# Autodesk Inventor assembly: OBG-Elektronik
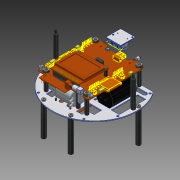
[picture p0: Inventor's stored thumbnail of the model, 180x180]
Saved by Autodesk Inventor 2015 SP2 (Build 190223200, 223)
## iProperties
Created: 2012-08
Part Number: OBG-Elektronik
Document SubType Name: Assembly
Designer: rYan
Mass: 772.839 g
Surface Area: 1589.28 cm^2
Volume: 316.547 cm^3
Density: 2.44147 g/cm^3
Author: rYan
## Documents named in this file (14)
- D:\TIGERs GIT\Hardware\mechanik\2016\Inventor\Elektronik\OBG-Elektronik.iam
- D:\TIGERs GIT\Hardware\mechanik\2016\Inventor\Elektronik\Elektronikhalter.ipt
- E:\Tigers SVN\mechanik\2013\Inventor\Kaufteile\Abstandsbolzen Typ A.ipt
- D:\TIGERs GIT\Hardware\mechanik\2016\Inventor\Elektronik\UBG-Mainboard.iam
- E:\Tigers SVN\mechanik\2013\Inventor\Kaufteile\Abstandsbolzen Typ B.ipt
- D:\TIGERs GIT\Hardware\mechanik\2016\Inventor\Inhaltscenter\en-US\DIN 7984\DIN 7984 - M4 x 6.ipt
- D:\TIGERs GIT\Hardware\mechanik\2016\Inventor\Inhaltscenter\en-US\DIN 7984\DIN 7984 - M3 x 6.ipt
- D:\TIGERs GIT\Hardware\mechanik\2016\Inventor\Kaufteile\Kondensator 30x50.ipt
- D:\TIGERs GIT\Hardware\mechanik\2016\Inventor\Kaufteile\Abstandsbolzen Typ B M3-8mm.ipt
- D:\TIGERs GIT\Hardware\mechanik\2016\Inventor\Elektronik\MG-Kickerboard.iam
- D:\TIGERs GIT\Hardware\mechanik\2016\Inventor\Kaufteile\Abstandsbolzen Typ A M4-65mm-SW8.ipt
- D:\TIGERs GIT\Hardware\mechanik\2016\Inventor\Kaufteile\Akku 4S1P 1800.ipt
- D:\TIGERs GIT\Hardware\mechanik\2016\Inventor\Kaufteile\Abstandsbolzen Typ B M3-30mm-SW6.ipt
- D:\TIGERs GIT\Hardware\mechanik\2016\Inventor\Kaufteile\Abstandsbolzen Typ B M4-55mm.ipt
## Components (31 placed, 11 different names)
1. Elektronikhalter:1 — Passend:152, Passend:288, Passend:289, Passend:290, Passend:291, Passend:292, Passend:293, Passend:294, Passend:295, Passend:296, Einfügen:7, Einfügen:8, Passend:356, Passend:357, Einfügen:9, Einfügen:10, Einfügen:11, Einfügen:12, Einfügen:15, Einfügen:16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
2. Akku 4S1P 1800:1 — Passend:359, Passend:360
3. UBG-Mainboard:1 [sub-assembly] — Einfügen:9, Einfügen:10
4. Abstandsbolzen Typ A M4-65mm-SW8:17 — Einfügen:8
5. Abstandsbolzen Typ A M4-65mm-SW8:18 — Einfügen:7
6. Abstandsbolzen Typ A M4-65mm-SW8:19 — Einfügen:12
7. Abstandsbolzen Typ A M4-65mm-SW8:20 — Einfügen:11
8. DIN 7984 M4 x 6:7 — Einfügen:15
9. DIN 7984 M4 x 6:8 — Einfügen:16
10. DIN 7984 M4 x 6:9 — Einfügen:18
11. DIN 7984 M4 x 6:10 — Einfügen:17
12. Abstandsbolzen Typ B M3-30mm-SW6:33 — Einfügen:22
13. Abstandsbolzen Typ B M3-30mm-SW6:34 — Einfügen:21
14. Abstandsbolzen Typ B M3-30mm-SW6:35 — Einfügen:23
15. Abstandsbolzen Typ B M3-30mm-SW6:36 — Einfügen:24
16. Abstandsbolzen Typ B M3-30mm-SW6:37 — Einfügen:25
17. Abstandsbolzen Typ B M4-55mm:38 — Einfügen:27
18. Abstandsbolzen Typ B M4-55mm:39 — Einfügen:26
19. DIN 7984 M4 x 6:5
20. DIN 7984 M4 x 6:6 — Passend:152
21. Kondensator 30x50:2 — Fluchtend:1, Fluchtend:3, Passend:357, Tangential:1, Passend:358
22. Kondensator 30x50:1 — Fluchtend:1, Fluchtend:3, Passend:356
23. Abstandsbolzen Typ B M3-8mm:29 — Passend:288, Passend:295
24. Abstandsbolzen Typ B M3-8mm:30 — Passend:290, Passend:292, Passend:298
25. Abstandsbolzen Typ B M3-8mm:31 — Passend:289, Passend:293, Passend:297, Passend:300
26. Abstandsbolzen Typ B M3-8mm:32 — Passend:291, Passend:294
27. MG-Kickerboard:1 [sub-assembly] — Passend:296, Passend:297, Passend:298, Passend:299
28. DIN 7984 M3 x 6:9 — Passend:299, Passend:300
29. DIN 7984 M3 x 6:10
30. DIN 7984 M3 x 6:11
31. DIN 7984 M3 x 6:12
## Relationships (39: Mate 19, Insert 17, Flush 2, Tangent 1)
- Fluchtend:1 [Flush]: Kondensator 30x50:2 ↔ Kondensator 30x50:1
- Fluchtend:3 [Flush]: Kondensator 30x50:2 ↔ Kondensator 30x50:1
- Passend:152 [Mate]: Elektronikhalter:1 ↔ DIN 7984 M4 x 6:6
- Passend:288 [Mate]: Elektronikhalter:1 ↔ Abstandsbolzen Typ B M3-8mm:29
- Passend:289 [Mate]: Elektronikhalter:1 ↔ Abstandsbolzen Typ B M3-8mm:31
- Passend:290 [Mate]: Elektronikhalter:1 ↔ Abstandsbolzen Typ B M3-8mm:30
- Passend:291 [Mate]: Elektronikhalter:1 ↔ Abstandsbolzen Typ B M3-8mm:32
- Passend:292 [Mate]: Elektronikhalter:1 ↔ Abstandsbolzen Typ B M3-8mm:30
- Passend:293 [Mate]: Elektronikhalter:1 ↔ Abstandsbolzen Typ B M3-8mm:31
- Passend:294 [Mate]: Elektronikhalter:1 ↔ Abstandsbolzen Typ B M3-8mm:32
- Passend:295 [Mate]: Elektronikhalter:1 ↔ Abstandsbolzen Typ B M3-8mm:29
- Passend:296 [Mate]: Elektronikhalter:1 ↔ MG-Kickerboard:1
- Passend:297 [Mate]: Abstandsbolzen Typ B M3-8mm:31 ↔ MG-Kickerboard:1
- Passend:298 [Mate]: Abstandsbolzen Typ B M3-8mm:30 ↔ MG-Kickerboard:1
- Passend:299 [Mate]: MG-Kickerboard:1 ↔ DIN 7984 M3 x 6:9
- Passend:300 [Mate]: Abstandsbolzen Typ B M3-8mm:31 ↔ DIN 7984 M3 x 6:9
- Einfügen:7 [Insert]: Elektronikhalter:1 ↔ Abstandsbolzen Typ A M4-65mm-SW8:18
- Einfügen:8 [Insert]: Elektronikhalter:1 ↔ Abstandsbolzen Typ A M4-65mm-SW8:17
- Passend:356 [Mate]: Elektronikhalter:1 ↔ Kondensator 30x50:1
- Passend:357 [Mate]: Elektronikhalter:1 ↔ Kondensator 30x50:2
- Einfügen:9 [Insert]: Elektronikhalter:1 ↔ UBG-Mainboard:1
- Einfügen:10 [Insert]: Elektronikhalter:1 ↔ UBG-Mainboard:1
- Einfügen:11 [Insert]: Elektronikhalter:1 ↔ Abstandsbolzen Typ A M4-65mm-SW8:20
- Einfügen:12 [Insert]: Elektronikhalter:1 ↔ Abstandsbolzen Typ A M4-65mm-SW8:19
- Einfügen:15 [Insert]: Elektronikhalter:1 ↔ DIN 7984 M4 x 6:7
- Einfügen:16 [Insert]: Elektronikhalter:1 ↔ DIN 7984 M4 x 6:8
- Einfügen:17 [Insert]: Elektronikhalter:1 ↔ DIN 7984 M4 x 6:10
- Einfügen:18 [Insert]: Elektronikhalter:1 ↔ DIN 7984 M4 x 6:9
- Tangential:1: Elektronikhalter:1 ↔ Kondensator 30x50:2
- Passend:358 [Mate]: Elektronikhalter:1 ↔ Kondensator 30x50:2
- Einfügen:21 [Insert]: Elektronikhalter:1 ↔ Abstandsbolzen Typ B M3-30mm-SW6:34
- Einfügen:22 [Insert]: Elektronikhalter:1 ↔ Abstandsbolzen Typ B M3-30mm-SW6:33
- Einfügen:23 [Insert]: Elektronikhalter:1 ↔ Abstandsbolzen Typ B M3-30mm-SW6:35
- Einfügen:24 [Insert]: Elektronikhalter:1 ↔ Abstandsbolzen Typ B M3-30mm-SW6:36
- Einfügen:25 [Insert]: Elektronikhalter:1 ↔ Abstandsbolzen Typ B M3-30mm-SW6:37
- Einfügen:26 [Insert]: Elektronikhalter:1 ↔ Abstandsbolzen Typ B M4-55mm:39
- Einfügen:27 [Insert]: Elektronikhalter:1 ↔ Abstandsbolzen Typ B M4-55mm:38
- Passend:359 [Mate]: Elektronikhalter:1 ↔ Akku 4S1P 1800:1
- Passend:360 [Mate]: Elektronikhalter:1 ↔ Akku 4S1P 1800:1
